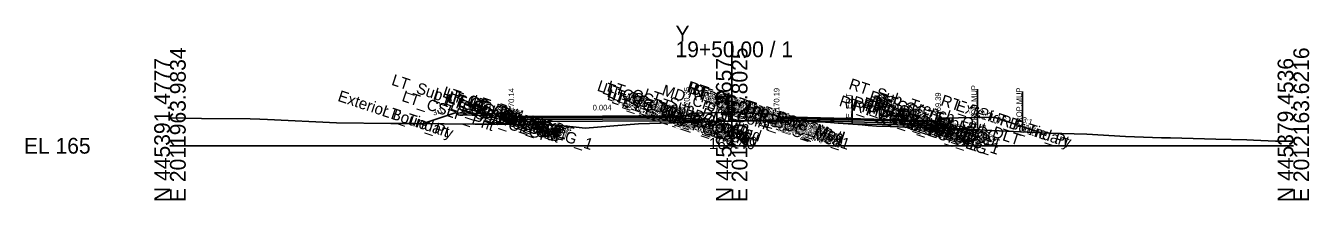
# Model space of a CAD drawing. Extents: x -26 to 3203, y -10 to 9532.
# Drawn here: x 974.3 to 1202.8, y 3490.3 to 3521.3 of the extents above; entities that cross this region are included whole.
import ezdxf

# ---------------------------------------------------------------- set-up
doc = ezdxf.new("R2010")
doc.units = 0
for name, color, linetype in [('Default', 7, 'Continuous'), ('Exist CMT Pavement', 7, 'Continuous'), ('Exist Cross Section Cell', 7, 'Continuous'), ('Exist XS Center Line Elevation Label', 7, 'Continuous'), ('Exist XS Ground Line', 7, 'Continuous'), ('Prop CMT Conc Surface', 7, 'Continuous'), ('Prop CMT Concrete Structures', 7, 'Continuous'), ('Prop CMT Pvmt Course 1', 7, 'Continuous'), ('Prop CMT Pvmt Course 1 CG', 7, 'Continuous'), ('Prop CMT Pvmt Course 2', 7, 'Continuous'), ('Prop CMT Pvmt Course 2 Wedge', 7, 'Continuous'), ('Prop CMT Pvmt Course 3', 7, 'Continuous'), ('Prop CMT Pvmt Course 3 Wedge', 7, 'Continuous'), ('Prop CMT Pvmt Surface', 7, 'Continuous'), ('Prop CMT Slope Grass', 7, 'Continuous'), ('Prop CMT Subgrade Earthwork', 7, 'Continuous'), ('Prop XS Hydro Elevations', 7, 'Continuous'), ('Prop XS Label Text', 7, 'Continuous'), ('Prop XS SE Text', 7, 'Continuous'), ('Prop XS Side Slope Text', 7, 'Continuous'), ('Scratch_Level_0', 7, 'Continuous')]:
    doc.layers.add(name, color=color, linetype=linetype)

msp = doc.modelspace()

# ---------------------------------------------------------------- linework, layer by layer
at = {"layer": 'Exist CMT Pavement'}
msp.add_lwpolyline([(1108.75, 3504.46), (1110.47, 3504.48), (1110.53, 3504.48), (1110.54, 3504.48), (1110.74, 3504.48), (1110.99, 3504.46), (1113.23, 3504.35), (1115.22, 3504.25), (1115.73, 3504.23), (1117.59, 3504.11), (1118.23, 3504.07), (1118.96, 3504.02), (1120.73, 3503.91), (1121.4, 3503.89), (1121.45, 3503.89), (1121.61, 3503.87), (1123.24, 3503.71), (1124.32, 3503.63), (1125.76, 3503.51), (1128.23, 3503.41), (1129.71, 3503.35), (1133.62, 3503.31)], dxfattribs=at)
at = {"layer": 'Exist Cross Section Cell'}
for p, q in [((1100, 3500), (1100, 3518.55)), ((1000, 3500), (1100, 3500)), ((1100, 3500), (1200, 3500))]:
    msp.add_line(p, q, dxfattribs=at)
at = {"layer": 'Exist XS Ground Line'}
msp.add_lwpolyline([(1000, 3504.98), (1005.62, 3504.83), (1014.26, 3504.81), (1015.97, 3504.76), (1017.37, 3504.69), (1029.63, 3504.06), (1039.31, 3503.94), (1043.39, 3503.95), (1054.28, 3503.87), (1058.5, 3503.87), (1064.42, 3503.78), (1068.49, 3503.71), (1073.9, 3503.12), (1083.4, 3503.89), (1093.26, 3504.2), (1095.17, 3504.24), (1096.51, 3504.3), (1098.56, 3504.38), (1099.5, 3504.4), (1100, 3504.4), (1100.72, 3504.4), (1101.06, 3504.41), (1103.44, 3504.44), (1105.74, 3504.46), (1106.88, 3504.46), (1108.24, 3504.45), (1110.53, 3504.48), (1110.99, 3504.46), (1113.23, 3504.35), (1115.22, 3504.25), (1115.73, 3504.23), (1117.59, 3504.11), (1118.23, 3504.07), (1118.96, 3504.02), (1120.73, 3503.91), (1121.45, 3503.89), (1123.24, 3503.71), (1124.32, 3503.63), (1125.76, 3503.51), (1128.23, 3503.41), (1129.71, 3503.35), (1133.62, 3503.31), (1156.55, 3502.23), (1163.24, 3502.05), (1170.13, 3501.66), (1176.51, 3501.41), (1178.1, 3501.41), (1186.17, 3501.17), (1191.74, 3501.03), (1192.9, 3501.02), (1196.8, 3500.84), (1198.87, 3500.84), (1200, 3500.84)], dxfattribs=at)
at = {"layer": 'Prop CMT Conc Surface'}
for points in [[(1056.27, 3505.73), (1051.27, 3505.83)], [(1091.25, 3505.35), (1092, 3505.35), (1092, 3505.52), (1092.76, 3505.77)], [(1060.77, 3505.14), (1060.77, 3505.64), (1060.27, 3505.64)], [(1062.77, 3505.23), (1060.77, 3505.14)], [(1108.75, 3505.17), (1108, 3505.19), (1108, 3505.35), (1107.24, 3505.6)], [(1134.75, 3504.52), (1136.75, 3504.39)], [(1136.75, 3504.39), (1136.75, 3504.89), (1137.25, 3504.89)]]:
    msp.add_lwpolyline(points, dxfattribs=at)
at = {"layer": 'Prop CMT Concrete Structures'}
for points in [[(1051.27, 3505.5), (1051.27, 3505.83)], [(1051.27, 3505.83), (1056.27, 3505.73)], [(1056.27, 3505.73), (1056.27, 3505.4)], [(1091.25, 3505.35), (1092, 3505.35), (1092, 3505.52), (1092.76, 3505.77)], [(1092.76, 3505.77), (1092.76, 3504.77)], [(1056.27, 3505.4), (1051.27, 3505.5)], [(1062.77, 3505.23), (1060.77, 3505.14), (1060.77, 3505.64), (1060.27, 3505.64)], [(1060.27, 3505.64), (1060.27, 3504.64), (1062.77, 3504.65)], [(1062.77, 3504.65), (1062.77, 3505.23)], [(1091.25, 3504.77), (1091.25, 3505.35)], [(1092.76, 3504.77), (1091.25, 3504.77)], [(1108.75, 3505.17), (1108, 3505.19), (1108, 3505.35), (1107.24, 3505.6)], [(1107.24, 3505.6), (1107.24, 3504.62)], [(1107.24, 3504.62), (1108.75, 3504.58)], [(1108.75, 3504.58), (1108.75, 3505.17)], [(1134.75, 3504.52), (1136.75, 3504.39), (1136.75, 3504.89), (1137.25, 3504.89)], [(1137.25, 3504.89), (1137.25, 3503.87), (1134.75, 3503.93)], [(1134.75, 3503.93), (1134.75, 3504.52)]]:
    msp.add_lwpolyline(points, dxfattribs=at)
at = {"layer": 'Prop CMT Pvmt Course 1'}
for points in [[(1091.25, 3505.35), (1062.77, 3505.23)], [(1062.77, 3505.23), (1062.77, 3504.98)], [(1062.77, 3504.98), (1091.25, 3505.1)], [(1091.25, 3505.1), (1091.25, 3505.35)], [(1091.25, 3505.1), (1091.25, 3505.1), (1091.25, 3505.1)], [(1108.75, 3505.17), (1134.75, 3504.52)], [(1108.75, 3504.92), (1108.75, 3505.17)], [(1134.75, 3504.27), (1133.62, 3504.3), (1108.75, 3504.92)], [(1108.75, 3504.92), (1108.75, 3504.92)], [(1134.75, 3504.52), (1134.75, 3504.27)]]:
    msp.add_lwpolyline(points, dxfattribs=at)
at = {"layer": 'Prop CMT Pvmt Course 1 CG'}
for points in [[(1062.77, 3504.65), (1059.77, 3504.64), (1059.44, 3504.3)], [(1059.44, 3504.3), (1062.77, 3504.31)], [(1062.77, 3504.31), (1062.77, 3504.65)], [(1091.25, 3504.77), (1093.26, 3504.78), (1093.59, 3504.44)], [(1091.25, 3504.43), (1091.25, 3504.77)], [(1093.59, 3504.44), (1091.25, 3504.43)], [(1108.75, 3504.58), (1106.74, 3504.63), (1106.41, 3504.31)], [(1106.41, 3504.31), (1108.75, 3504.25)], [(1108.75, 3504.25), (1108.75, 3504.58)], [(1134.75, 3503.93), (1137.75, 3503.86), (1138.09, 3503.52)], [(1134.75, 3503.6), (1134.75, 3503.93)], [(1138.09, 3503.52), (1134.75, 3503.6)]]:
    msp.add_lwpolyline(points, dxfattribs=at)
at = {"layer": 'Prop CMT Pvmt Course 2'}
for points in [[(1091.25, 3505.1), (1062.77, 3504.98)], [(1062.77, 3504.98), (1062.77, 3504.65)], [(1062.77, 3504.65), (1091.25, 3504.77)], [(1091.25, 3504.77), (1091.25, 3505.1)], [(1108.75, 3504.92), (1108.75, 3504.92)], [(1121.45, 3504.27), (1121.45, 3504.6)], [(1121.45, 3504.6), (1134.75, 3504.27)], [(1134.75, 3503.93), (1121.45, 3504.27)], [(1134.75, 3504.27), (1134.75, 3503.93)]]:
    msp.add_lwpolyline(points, dxfattribs=at)
msp.add_lwpolyline([(1108.75, 3504.92), (1108.75, 3504.58), (1108.75, 3504.58)], close=True, dxfattribs=at)
at = {"layer": 'Prop CMT Pvmt Course 2 Wedge'}
for points in [[(1108.75, 3504.58), (1108.75, 3504.92)], [(1108.75, 3504.92), (1110.47, 3504.87), (1110.53, 3504.87), (1110.54, 3504.87), (1110.74, 3504.87), (1110.99, 3504.86), (1113.23, 3504.81), (1115.22, 3504.76), (1115.73, 3504.74), (1117.59, 3504.7), (1118.23, 3504.68), (1118.96, 3504.66), (1120.73, 3504.62), (1121.45, 3504.6)], [(1121.45, 3504.27), (1120.73, 3504.29), (1118.96, 3504.33), (1118.23, 3504.35), (1117.59, 3504.36), (1115.73, 3504.41), (1115.22, 3504.42), (1113.23, 3504.47), (1110.99, 3504.53), (1110.74, 3504.53), (1110.54, 3504.54), (1110.53, 3504.54), (1110.47, 3504.54), (1108.75, 3504.58)], [(1121.45, 3504.6), (1121.45, 3504.27), (1121.45, 3504.27)]]:
    msp.add_lwpolyline(points, dxfattribs=at)
at = {"layer": 'Prop CMT Pvmt Course 3'}
for points in [[(1091.25, 3504.77), (1062.77, 3504.65)], [(1062.77, 3504.65), (1062.77, 3504.31)], [(1062.77, 3504.31), (1091.25, 3504.43)], [(1091.25, 3504.43), (1091.25, 3504.77)], [(1108.75, 3504.58), (1108.75, 3504.58), (1108.75, 3504.25), (1108.75, 3504.25)], [(1108.75, 3504.25), (1108.75, 3504.58)], [(1121.45, 3504.27), (1134.75, 3503.93)], [(1121.45, 3503.93), (1121.45, 3504.27)], [(1134.75, 3503.6), (1121.45, 3503.93)], [(1134.75, 3503.93), (1134.75, 3503.6)]]:
    msp.add_lwpolyline(points, dxfattribs=at)
at = {"layer": 'Prop CMT Pvmt Course 3 Wedge'}
for points in [[(1108.75, 3504.46), (1108.75, 3504.58)], [(1108.75, 3504.58), (1110.47, 3504.54), (1110.53, 3504.54), (1110.54, 3504.54), (1110.74, 3504.53), (1110.99, 3504.53), (1113.23, 3504.47), (1115.22, 3504.42), (1115.73, 3504.41), (1117.59, 3504.36), (1118.23, 3504.35), (1118.96, 3504.33), (1120.73, 3504.29), (1121.45, 3504.27)], [(1133.62, 3503.31), (1129.71, 3503.35), (1128.23, 3503.41), (1125.76, 3503.51), (1124.32, 3503.63), (1123.24, 3503.71), (1121.61, 3503.87), (1121.45, 3503.89), (1121.4, 3503.89), (1120.73, 3503.91), (1118.96, 3504.02), (1118.23, 3504.07), (1117.59, 3504.11), (1115.73, 3504.23), (1115.22, 3504.25), (1113.23, 3504.35), (1110.99, 3504.46), (1110.74, 3504.48), (1110.54, 3504.48), (1110.53, 3504.48), (1110.47, 3504.48), (1108.75, 3504.46)], [(1121.45, 3504.27), (1121.45, 3503.89)]]:
    msp.add_lwpolyline(points, dxfattribs=at)
at = {"layer": 'Prop CMT Pvmt Surface'}
for points in [[(1091.25, 3505.35), (1062.77, 3505.23)], [(1108.75, 3505.17), (1134.75, 3504.52)]]:
    msp.add_lwpolyline(points, dxfattribs=at)
at = {"layer": 'Prop CMT Slope Grass'}
for points in [[(1050.77, 3505.83), (1045.09, 3503.94)], [(1060.27, 3505.64), (1050.77, 3505.83)], [(1092.76, 3505.77), (1100, 3505.91)], [(1107.24, 3505.6), (1100, 3505.91)], [(1137.25, 3504.89), (1146.75, 3505.08)], [(1146.75, 3505.08), (1155.1, 3502.3)]]:
    msp.add_lwpolyline(points, dxfattribs=at)
at = {"layer": 'Prop CMT Subgrade Earthwork'}
for points in [[(1094.96, 3505.81), (1093.59, 3504.44)], [(1105.03, 3505.7), (1106.41, 3504.31)], [(1062.77, 3504.31), (1059.44, 3504.3), (1058.05, 3505.69)], [(1091.25, 3504.43), (1062.77, 3504.31)], [(1062.77, 3504.31), (1062.77, 3504.31)], [(1093.59, 3504.44), (1091.25, 3504.43)], [(1091.25, 3504.43), (1091.25, 3504.43)], [(1091.25, 3504.43), (1091.25, 3504.43)], [(1106.41, 3504.31), (1108.75, 3504.25)], [(1108.75, 3504.25), (1108.73, 3504.46)], [(1108.75, 3504.25), (1108.75, 3504.25)], [(1108.75, 3504.25), (1108.75, 3504.25)], [(1121.45, 3503.93), (1134.75, 3503.6)], [(1121.45, 3503.93), (1121.45, 3503.89)], [(1134.75, 3503.6), (1138.09, 3503.52), (1139.51, 3504.93)], [(1134.75, 3503.6), (1134.75, 3503.6)]]:
    msp.add_lwpolyline(points, dxfattribs=at)
at = {"layer": 'Prop XS Label Text'}
for p, q in [((1099.5, 3509.4), (1099.5, 3504.4)), ((1121.45, 3508.89), (1121.45, 3503.89)), ((1143.77, 3510.07), (1143.77, 3503.07)), ((1151.79, 3509.65), (1151.79, 3502.65))]:
    msp.add_line(p, q, dxfattribs=at)

# ---------------------------------------------------------------- texts
at = {"layer": 'Default'}
msp.add_text('-', height=0.0001, dxfattribs=at).set_placement((1000, 3500))
at = {"layer": 'Exist Cross Section Cell'}
for s, p in [('Y', (1090, 3518.55)), ('19+50.00 / 1', (1090, 3515.75)), ('EL 165', (974, 3498.6))]:
    msp.add_text(s, height=2.8, dxfattribs=at).set_placement(p)
for s, p in [('E 2011963.9834', (1002.8, 3490)), ('E 2012063.8025', (1102.8, 3490)), ('E 2012163.6216', (1202.8, 3490)), ('N 445391.4777', (1000, 3490)), ('N 445385.4657', (1100, 3490)), ('N 445379.4536', (1200, 3490))]:
    msp.add_text(s, height=2.8, rotation=90, dxfattribs=at).set_placement(p)
at = {"layer": 'Exist XS Center Line Elevation Label'}
msp.add_text('169.40', height=2, dxfattribs=at).set_placement((1095.95, 3499.4))
at = {"layer": 'Prop XS Hydro Elevations'}
for s, p in [('170.35', (1092.5, 3506.35)), ('170.14', (1061.27, 3506.14)), ('170.19', (1108.5, 3506.19)), ('169.39', (1137.25, 3505.39))]:
    msp.add_text(s, height=1, rotation=90, dxfattribs=at).set_placement(p)
at = {"layer": 'Prop XS Label Text'}
for s, p in [('PROP.MUP', (1143.67, 3503.64)), ('PROP.MUP', (1151.69, 3503.22)), ('E. EOT', (1099.4, 3505.42)), ('E. EOT', (1121.35, 3504.91))]:
    msp.add_text(s, height=1, rotation=90, dxfattribs=at).set_placement(p)
at = {"layer": 'Prop XS SE Text'}
for s, rotation, p in [('0.004', 0.2394, (1075.26, 3506.28)), ('0.025', 358.5679, (1129.11, 3505.66))]:
    msp.add_text(s, height=1, rotation=rotation, dxfattribs=at).set_placement(p)
at = {"layer": 'Prop XS Side Slope Text'}
for rotation, p in [(18.4349, (1046.94, 3505.35)), (341.5651, (1151.62, 3504.24))]:
    msp.add_text('3:1', height=1, rotation=rotation, dxfattribs=at).set_placement(p)
at = {"layer": 'Scratch_Level_0'}
for s, p in [('LT_Sub_Trench_Out_DLT', (1039.3, 3510.88)), ('LT_CG_Top_Face', (1048.37, 3508.72)), ('LT_CG_Top_Face_Med', (1075.91, 3509.83)), ('LT_CG_Top_Gut_Med', (1076.83, 3509.35)), ('LT_CG_Top_BOC_Med', (1077.64, 3509.76)), ('LT_CG_Bot_BOC_Med', (1077.67, 3508.75)), ('MD_Crown Point', (1087.42, 3509.05)), ('RT_CG_Top_Face_Med', (1091.86, 3509.68)), ('RT_CG_Top_BOC_Med', (1092.07, 3509.6)), ('RT_CG_Bot_BOC_Med', (1092.1, 3508.61)), ('RT_CG_Top_Gut_Med', (1092.79, 3509.2)), ('RT_Sub_Trench_Out_DLT', (1120.71, 3510.14)), ('Exterior Boundary', (1029.73, 3508.01)), ('LT_CSLP_Pnt', (1041.13, 3507.99)), ('LT_CG1_Shelf_Out', (1046.7, 3507.94)), ('LT_CG_Top_BOC', (1048.84, 3508.4)), ('LT_CG_Bot_BOC', (1048.87, 3507.38)), ('LT_CG_Top_Gut', (1049.29, 3507.91)), ('LT_Sub_OEOT_CG_1', (1049.38, 3507.72)), ('LT_Sub_OEOP', (1049.74, 3506.48)), ('LT_CG_Bot_IE', (1052.89, 3506.89)), ('LT_Sub_OEOT', (1053.04, 3506.5)), ('LT_PV2_OEOT', (1053.13, 3507.14)), ('LT_PV3_OEOT', (1053.13, 3506.81)), ('LT_PV1_OEOT', (1053.67, 3507.21)), ('LT_CG_Bot_IE_Med', (1077.71, 3508.23)), ('LT_Sub_IEOT_CG_1', (1078.47, 3507.64)), ('LT_Sub_OEEOP', (1080.7, 3506.9)), ('LT_PV2_OEEOP', (1080.79, 3507.53)), ('LT_PV3_OEEOP', (1080.79, 3507.2)), ('LT_Sub_IEEOP', (1081.31, 3506.69)), ('LT_PV2_IEEOP', (1081.4, 3507.33)), ('LT_CG1_Shelf_In', (1081.72, 3507.57)), ('LT_Sub_PGL', (1082.51, 3506.29)), ('LT_PV2_PGL', (1082.6, 3506.93)), ('LT_PV1_PGL', (1083.14, 3507)), ('LT_Sub_DLT_In', (1084.16, 3508.36)), ('LT_Sub_IEOP', (1084.51, 3506.42)), ('RT_Sub_DLT_In', (1094.18, 3508.26)), ('RT_CG1_Shelf_In', (1095.16, 3507.44)), ('RT_CG_Bot_IE_Med', (1095.17, 3508.06)), ('RT_PV_Sub_Tie_In', (1095.63, 3507.77)), ('RT_Sub_IEOT_CG_1', (1095.93, 3507.47)), ('RT_PV_IEEOP_EG', (1097.18, 3507.26)), ('RT_Sub_IEOP', (1097.28, 3506.3)), ('RT_Sub_IEEOP', (1098.77, 3506.52)), ('RT_PV2_IEEOP', (1098.86, 3507.16)), ('RT_PV3_IEEOP', (1098.86, 3506.83)), ('RT_PV2_PGL', (1100.05, 3506.76)), ('RT_PV3_PGL', (1100.05, 3506.43)), ('RT_PV1_PGL', (1100.59, 3506.83)), ('RT_PV_Sub_Tie_Out', (1118.99, 3507.14)), ('RT_Sub_OEOT_CG_1', (1121.32, 3507.03)), ('RT_PV_OEEOP_EG', (1121.44, 3506.32)), ('RT_PV2_OEEOP', (1123.12, 3506.74)), ('RT_PV3_OEEOP', (1123.12, 3506.41)), ('RT_CG_Top_Face', (1124.3, 3507.98)), ('RT_CG1_Shelf_Out', (1124.63, 3507.18)), ('RT_CG_Bot_IE', (1124.82, 3506.19)), ('RT_PV2_OEOT', (1125.07, 3506.44)), ('RT_CG_Top_Gut', (1125.23, 3507.17)), ('RT_PV1_OEOT', (1125.6, 3506.51)), ('RT_CG_Top_BOC', (1125.77, 3507.66)), ('RT_CG_Bot_BOC', (1125.8, 3506.63)), ('RT_CSLP_Pnt', (1137.07, 3507.25)), ('Exterior Boundary', (1139.74, 3506.36)), ('LT_Tie_Pt', (1037.6, 3505.38)), ('RT_Sub_PGL', (1099.96, 3506.13)), ('RT_Sub_OEEOP', (1123.03, 3506.11)), ('RT_Sub_OEOT', (1124.98, 3505.8)), ('RT_PV3_OEOT', (1125.07, 3506.11)), ('RT_Sub_OEOP', (1128.35, 3505.71)), ('RT_Tie_Pt', (1147.56, 3503.75))]:
    msp.add_text(s, height=2, rotation=341.5651, dxfattribs=at).set_placement(p)

doc.saveas('drawing.dxf')
